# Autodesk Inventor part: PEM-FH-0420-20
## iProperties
Created: 2009-01
Part Number: PEM-FH-0420-20
Document SubType Name: Modeling
Designer: claivier
Norme de conversion: STEP AP214IS
Nom du fichier: PEM-FH-0420-20.STEP
Préprocesseur: SolidWorks 2008
Postprocesseur: Build: 344a, Release: 11 SP2 - Date: Fri 08/18/2006
Unités envoyées: INCHES
Incertitude: 1e-05
Author: claivier
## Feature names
1. Base1
